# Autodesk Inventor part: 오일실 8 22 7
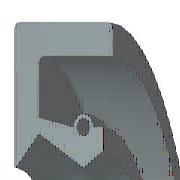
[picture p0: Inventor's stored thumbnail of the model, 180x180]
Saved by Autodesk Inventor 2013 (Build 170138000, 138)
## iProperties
IsCustomPart: 1
Created: 2012-02
Part Number: 오일실 8 22 7
Material: 고무
Description: 오일-실
Document SubType Name: Modeling
Standard: KS B 2804
Designer: mduedu
Standards Organization: KS
Language: ko-KR
Size Designation: D - 8 22 7
Categories: <MemberInstance><Categories><Category DisplayName="샤프트 부품" InternalName="7f7aeb1f-a693-4053-b835-cee3144e0d98" Mnemonic="SHFT"><Category DisplayName="실링" Intern
Density: 0.93 g/cm^3
Mass: 1.28441 g
Surface Area: 18.2787 cm^2
Volume: 1.38108 cm^3
Author: mduedu
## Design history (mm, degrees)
revolve "본체" stored, may be unused: angle "d17" = 90 deg
revolve "스프링1" stored, may be unused: angle "d18" = 90 deg
body "Solid1"
sketch "스케치1"
  geometry: L1 (0, 11)-(7, 11); L2 (7, 9.25)-(1.75, 9.25); L3 (1.75, 5.75)-(4.9, 4); L4 (4.9, 4)-(0, 4); L5 (0, 0)-(9.586, 0) reference; L6 (4.9, 4)-(6.3, 4.875); L7 (0, 18)-(0, -3) reference; L8 (-1.941, 0)-(11.507, 0) reference; L9 (4.2, 6.1)-(1.75, 6.59); L10 (1.75, 6.59)-(1.75, 9.25); L11 (0, 11)-(0, 4.088); L12 (4.9, 4)-(0, 4); L13 (1.75, 5.75)-(0.152, 4.028); L14 (7, 11)-(7, 9.25); L15 (5.6, 6.1)-(6.3, 6.1); L16 (6.3, 6.1)-(6.3, 4.875); C1 r 0.455 at (4.9, 6.1); A1 r 0.7 centre (4.9, 6.1) between (5.6, 6.1) and (4.2, 6.1); A2 r 0.088 centre (0.088, 4.088) between (0, 4.088) and (0.152, 4.028); 1 further point
  constraints: 28 end point, 5 horizontal alignment, 5 point on line, 4 point on circle, 4 vertical alignment, 3 centre point, 3 tangent, 2 collinear, 2 horizontal, 2 perpendicular, 1 coincident, 1 parallel
  dimensions: "d0" = 22 diameter of L1 L5 (= SD2); "d1" = 1.75 distance of L1.end L2.start (= SD); "d2" = 0.91 diameter of C1 (= SPDI); "d3" = 1.4 diameter of A1 (= SPDA); "d4" = 8 diameter of L3.end L5 (= NND); "d5" = 11.5 diameter of L3.start L5 (= TKDM); "d7" = 13.18 diameter of L9.end L5 (= TKDM + 0.24 x SWDT); "d8" = 1.75 distance between parallel lines of L11 L10 (= SD); "d9" = 4.9 distance from line of L11 C1.centre (= SPDST); "d10" = 12.2 diameter of C1.centre L5 (= HLDM); "d11" = 0.0875 radius of A2 (= 0.25 x LAB); "d12" = 6.3 distance between parallel lines of L11 L16 (= SDI); "d13" = 9.75 diameter of L6.end L5 (= ABDM); "d14" = 7 distance from line of L11 L1.end (= SWDT)
fillet "모깎기1" dims "d6" = 0.3 (= RR)
other parameters: "SD2" = 22 [user parameter; used in 1 equation term], "SWDT" = 7 [user parameter; used in 2 equation terms], "RR" = 0.3 [user parameter; used in 1 equation term], "SD" = 1.75 [user parameter; used in 2 equation terms], "NND" = 8 [user parameter; used in 1 equation term], "SPDA" = 1.4 [user parameter; used in 1 equation term], "SPDI" = 0.91 [user parameter; used in 1 equation term], "TKDM" = 11.5 [user parameter; used in 2 equation terms], "HLDM" = 12.2 [user parameter; used in 1 equation term], "ABDM" = 9.75 [user parameter; used in 1 equation term], "SDI" = 6.3 [user parameter; used in 1 equation term], "SPDST" = 4.9 [user parameter; used in 1 equation term], "LAB" = 0.35 [user parameter; used in 1 equation term], "d15" = 0, "d16" = 0, "d19" = 0
